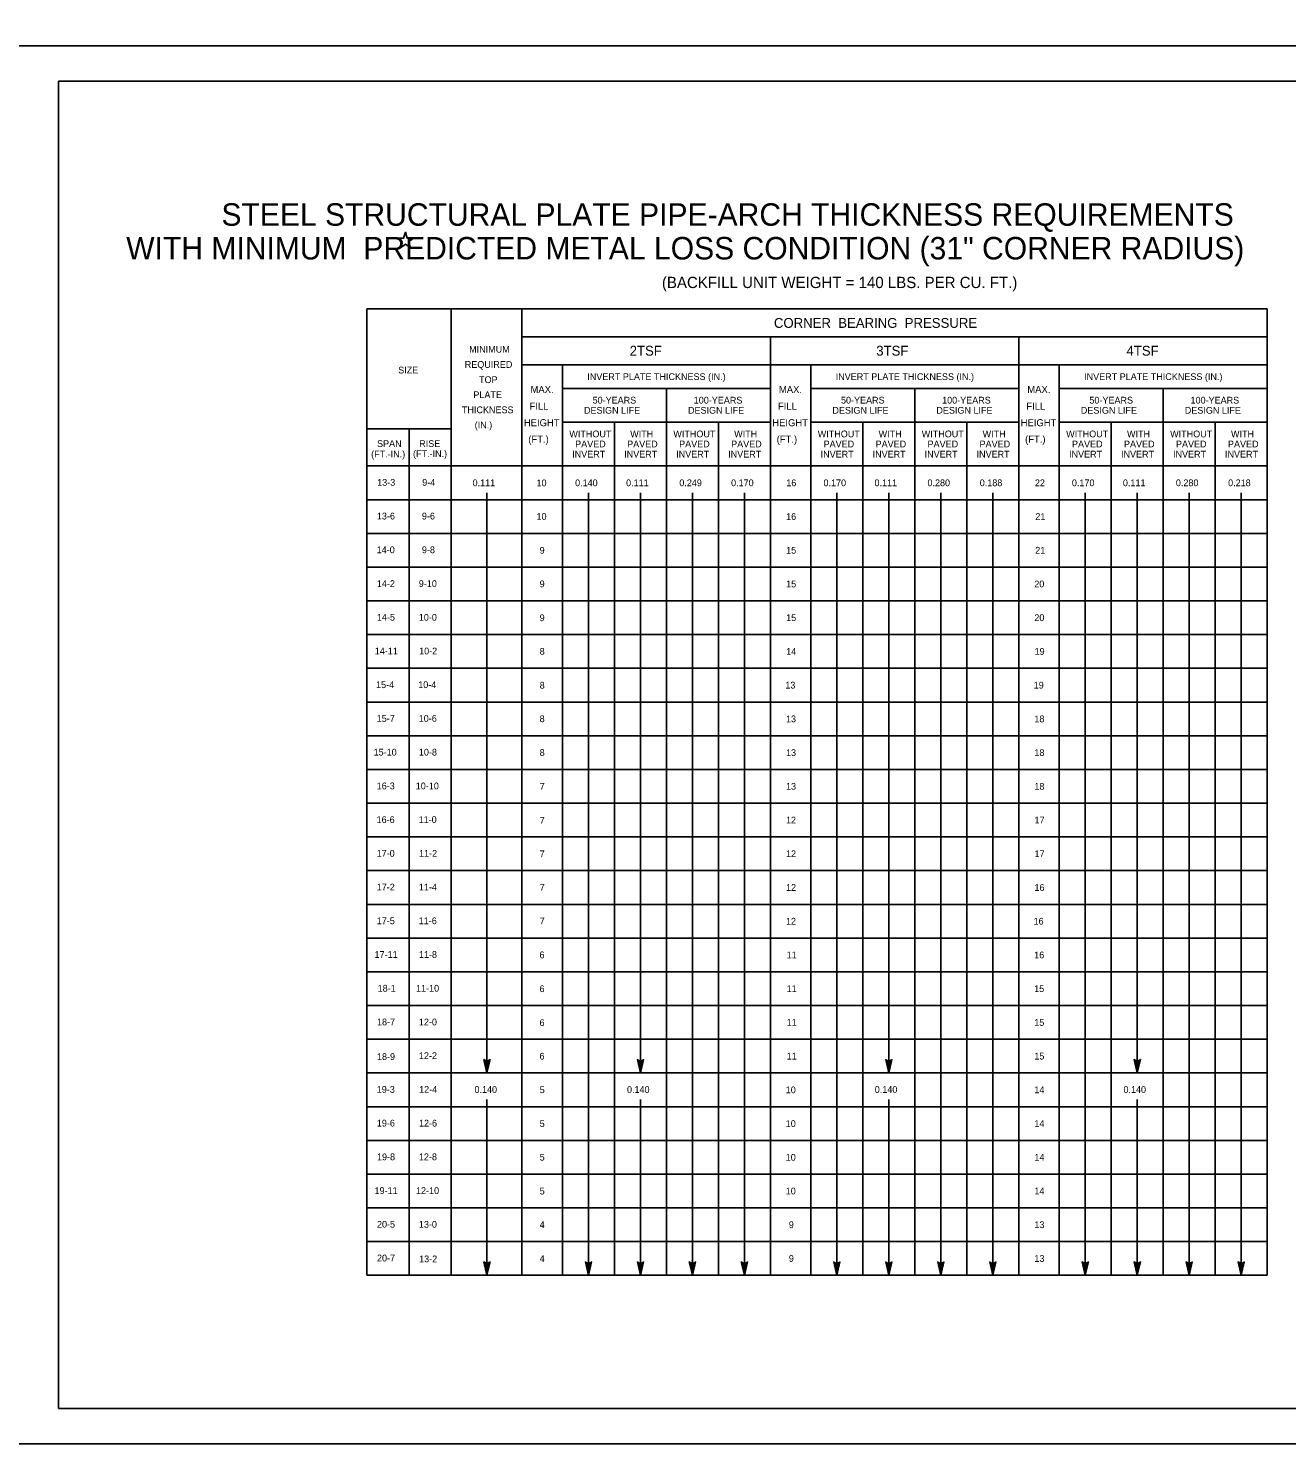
# Model space of a CAD drawing. Extents: x 591 to 2288, y -189 to 2187.
# Drawn here: x 1459 to 1994, y 405 to 1007 of the extents above; entities that cross this region are included whole.
import ezdxf

# ---------------------------------------------------------------- set-up
doc = ezdxf.new("R2010")
doc.units = 0
for name, color, linetype in [('1', 7, 'Continuous'), ('2', 7, 'Continuous'), ('PLT-BNDY', 7, 'Continuous')]:
    doc.layers.add(name, color=color, linetype=linetype)

msp = doc.modelspace()

# ---------------------------------------------------------------- linework, layer by layer
at = {"layer": '1'}
for p, q in [((1603.34, 887.46), (1985.97, 887.46)), ((1603.34, 887.46), (1603.34, 476.76)), ((1639.17, 887.46), (1639.17, 476.76)), ((1669.26, 887.46), (1669.26, 476.76)), ((1985.97, 887.46), (1985.97, 476.76)), ((1669.26, 875.59), (1985.97, 875.59)), ((1774.83, 875.59), (1774.83, 476.76)), ((1880.4, 875.59), (1880.4, 476.76)), ((1669.26, 863.72), (1774.83, 863.72)), ((1686.45, 863.72), (1686.45, 476.76)), ((1774.83, 863.72), (1880.4, 863.72)), ((1792.02, 863.72), (1792.02, 476.76)), ((1880.4, 863.72), (1985.97, 863.72)), ((1897.59, 863.72), (1897.59, 476.76)), ((1686.45, 853.69), (1774.83, 853.69)), ((1730.64, 853.69), (1730.64, 476.76)), ((1792.02, 853.69), (1880.4, 853.69)), ((1836.21, 853.69), (1836.21, 476.76)), ((1897.59, 853.69), (1985.97, 853.69)), ((1941.78, 853.69), (1941.78, 476.76)), ((1639.17, 836.49), (1603.34, 836.49)), ((1621.25, 836.49), (1621.25, 476.76)), ((1686.45, 839.36), (1730.64, 839.36)), ((1708.54, 839.36), (1708.54, 476.76)), ((1774.83, 839.36), (1730.64, 839.36)), ((1752.74, 839.36), (1752.74, 476.76)), ((1792.02, 839.36), (1836.21, 839.36)), ((1814.11, 839.36), (1814.11, 476.76)), ((1880.4, 839.36), (1836.21, 839.36)), ((1858.31, 839.36), (1858.31, 476.76)), ((1897.59, 839.36), (1941.78, 839.36)), ((1919.68, 839.36), (1919.68, 476.76)), ((1985.97, 839.36), (1941.78, 839.36)), ((1963.88, 839.36), (1963.88, 476.76)), ((1985.97, 820.72), (1603.34, 820.72)), ((1603.34, 806.39), (1985.97, 806.39)), ((1654.35, 809.3), (1654.35, 562.75)), ((1697.49, 809.3), (1697.49, 479.62)), ((1719.59, 809.3), (1719.59, 562.75)), ((1741.68, 809.3), (1741.68, 479.62)), ((1763.79, 809.3), (1763.79, 479.62)), ((1803.06, 809.3), (1803.06, 479.62)), ((1825.16, 809.3), (1825.16, 562.75)), ((1847.26, 809.3), (1847.26, 479.62)), ((1869.36, 809.3), (1869.36, 479.62)), ((1908.63, 809.3), (1908.63, 479.62)), ((1930.73, 809.3), (1930.73, 562.75)), ((1952.83, 809.3), (1952.83, 479.62)), ((1974.93, 809.3), (1974.93, 479.62)), ((1603.34, 792.06), (1985.97, 792.06)), ((1603.34, 777.73), (1985.97, 777.73)), ((1603.34, 763.4), (1985.97, 763.4)), ((1603.34, 749.06), (1985.97, 749.06)), ((1603.34, 734.73), (1985.97, 734.73)), ((1603.34, 720.4), (1985.97, 720.4)), ((1603.34, 706.07), (1985.97, 706.07)), ((1603.34, 691.74), (1985.97, 691.74)), ((1603.34, 677.4), (1985.97, 677.4)), ((1603.34, 663.07), (1985.97, 663.07)), ((1603.34, 648.74), (1985.97, 648.74)), ((1603.34, 634.41), (1985.97, 634.41)), ((1603.34, 620.08), (1985.97, 620.08)), ((1603.34, 605.74), (1985.97, 605.74)), ((1603.34, 591.41), (1985.97, 591.41)), ((1603.34, 577.08), (1985.97, 577.08)), ((1603.34, 562.75), (1985.97, 562.75)), ((1603.34, 548.42), (1985.97, 548.42)), ((1654.35, 479.62), (1654.35, 551.52)), ((1719.59, 479.62), (1719.59, 551.52)), ((1825.16, 479.62), (1825.16, 551.52)), ((1930.73, 479.62), (1930.73, 551.52)), ((1603.34, 534.08), (1985.97, 534.08)), ((1603.34, 519.75), (1985.97, 519.75)), ((1603.34, 505.42), (1985.97, 505.42)), ((1603.34, 491.09), (1985.97, 491.09)), ((1603.34, 476.76), (1985.97, 476.76))]:
    msp.add_line(p, q, dxfattribs=at)
for points in [[(1655.33, 568.17), (1654.77, 567.97), (1654.35, 562.75), (1655.33, 568.17), (1655.67, 568.45), (1654.35, 562.75), (1653.98, 567.97), (1653.42, 568.16), (1654.35, 562.75), (1653.05, 568.45), (1653.42, 568.16)], [(1720.57, 568.17), (1720.01, 567.97), (1719.59, 562.75), (1720.57, 568.17), (1720.92, 568.45), (1719.59, 562.75), (1719.22, 567.97), (1718.66, 568.16), (1719.59, 562.75), (1718.29, 568.45), (1718.66, 568.16)], [(1826.14, 568.17), (1825.58, 567.97), (1825.16, 562.75), (1826.14, 568.17), (1826.49, 568.45), (1825.16, 562.75), (1824.79, 567.97), (1824.23, 568.16), (1825.16, 562.75), (1823.86, 568.45), (1824.23, 568.16)], [(1931.71, 568.17), (1931.15, 567.97), (1930.73, 562.75), (1931.71, 568.17), (1932.06, 568.45), (1930.73, 562.75), (1930.36, 567.97), (1929.8, 568.16), (1930.73, 562.75), (1929.43, 568.45), (1929.8, 568.16)], [(1655.33, 482.18), (1654.77, 481.98), (1654.35, 476.76), (1655.33, 482.18), (1655.67, 482.46), (1654.35, 476.76), (1653.98, 481.98), (1653.42, 482.17), (1654.35, 476.76), (1653.05, 482.46), (1653.42, 482.17)], [(1698.47, 482.18), (1697.91, 481.98), (1697.49, 476.76), (1698.47, 482.18), (1698.81, 482.46), (1697.49, 476.76), (1697.12, 481.98), (1696.56, 482.17), (1697.49, 476.76), (1696.19, 482.46), (1696.56, 482.17)], [(1720.57, 482.18), (1720.01, 481.98), (1719.59, 476.76), (1720.57, 482.18), (1720.92, 482.46), (1719.59, 476.76), (1719.22, 481.98), (1718.66, 482.17), (1719.59, 476.76), (1718.29, 482.46), (1718.66, 482.17)], [(1742.66, 482.18), (1742.1, 481.98), (1741.68, 476.76), (1742.66, 482.18), (1743.01, 482.46), (1741.68, 476.76), (1741.31, 481.98), (1740.75, 482.17), (1741.68, 476.76), (1740.38, 482.46), (1740.75, 482.17)], [(1764.77, 482.18), (1764.2, 481.98), (1763.79, 476.76), (1764.77, 482.18), (1765.11, 482.46), (1763.79, 476.76), (1763.41, 481.98), (1762.85, 482.17), (1763.79, 476.76), (1762.48, 482.46), (1762.85, 482.17)], [(1804.04, 482.18), (1803.48, 481.98), (1803.06, 476.76), (1804.04, 482.18), (1804.39, 482.46), (1803.06, 476.76), (1802.69, 481.98), (1802.13, 482.17), (1803.06, 476.76), (1801.76, 482.46), (1802.13, 482.17)], [(1826.14, 482.18), (1825.58, 481.98), (1825.16, 476.76), (1826.14, 482.18), (1826.49, 482.46), (1825.16, 476.76), (1824.79, 481.98), (1824.23, 482.17), (1825.16, 476.76), (1823.86, 482.46), (1824.23, 482.17)], [(1848.24, 482.18), (1847.67, 481.98), (1847.26, 476.76), (1848.24, 482.18), (1848.58, 482.46), (1847.26, 476.76), (1846.88, 481.98), (1846.33, 482.17), (1847.26, 476.76), (1845.95, 482.46), (1846.33, 482.17)], [(1870.34, 482.18), (1869.77, 481.98), (1869.36, 476.76), (1870.34, 482.18), (1870.68, 482.46), (1869.36, 476.76), (1868.98, 481.98), (1868.42, 482.17), (1869.36, 476.76), (1868.05, 482.46), (1868.42, 482.17)], [(1909.61, 482.18), (1909.05, 481.98), (1908.63, 476.76), (1909.61, 482.18), (1909.96, 482.46), (1908.63, 476.76), (1908.26, 481.98), (1907.7, 482.17), (1908.63, 476.76), (1907.33, 482.46), (1907.7, 482.17)], [(1931.71, 482.18), (1931.15, 481.98), (1930.73, 476.76), (1931.71, 482.18), (1932.06, 482.46), (1930.73, 476.76), (1930.36, 481.98), (1929.8, 482.17), (1930.73, 476.76), (1929.43, 482.46), (1929.8, 482.17)], [(1953.81, 482.18), (1953.24, 481.98), (1952.83, 476.76), (1953.81, 482.18), (1954.15, 482.46), (1952.83, 476.76), (1952.45, 481.98), (1951.9, 482.17), (1952.83, 476.76), (1951.52, 482.46), (1951.9, 482.17)], [(1975.91, 482.18), (1975.34, 481.98), (1974.93, 476.76), (1975.91, 482.18), (1976.25, 482.46), (1974.93, 476.76), (1974.56, 481.98), (1973.99, 482.17), (1974.93, 476.76), (1973.62, 482.46), (1973.99, 482.17)]]:
    msp.add_lwpolyline(points, dxfattribs=at)
at = {"layer": '2'}
for p, q in [((1472.34, 420.21), (1472.34, 984.21)), ((1472.34, 984.21), (2258.34, 984.21)), ((1619.7, 916.41), (1619.7, 916.41)), ((2258.34, 420.21), (1472.34, 420.21))]:
    msp.add_line(p, q, dxfattribs=at)
msp.add_lwpolyline([(1616.27, 917.52), (1618.91, 917.51), (1619.73, 920.03), (1620.53, 917.49), (1623.18, 917.52), (1621.02, 915.96), (1621.86, 913.47), (1619.7, 915.02), (1617.59, 913.47), (1618.41, 915.97), (1616.27, 917.52)], dxfattribs=at)
at = {"layer": 'PLT-BNDY'}
for points in [[(1432.34, 1593.21), (2273.34, 1593.21), (2273.34, 999.21), (1432.34, 999.21)], [(1432.34, 405.21), (2273.34, 405.21), (2273.34, 999.21), (1432.34, 999.21)]]:
    msp.add_lwpolyline(points, close=True, dxfattribs=at)

# ---------------------------------------------------------------- texts
at = {"layer": '1'}
for s, height, p in [('STEEL STRUCTURAL PLATE PIPE-ARCH THICKNESS REQUIREMENTS', 9.5546, (1541.53, 922.8)), ('WITH MINIMUM  PREDICTED METAL LOSS CONDITION (31" CORNER RADIUS)', 9.5546, (1501.06, 908.48)), ('(BACKFILL UNIT WEIGHT = 140 LBS. PER CU. FT.)', 4.7773, (1728.73, 896.32)), ('CORNER  BEARING  PRESSURE', 4.1801, (1776.34, 879.41)), ('MINIMUM', 2.866, (1646.8, 868.9)), ('2TSF', 4.18, (1715.03, 867.6)), ('3TSF', 4.18, (1819.82, 867.6)), ('4TSF', 4.18, (1926.17, 867.6)), ('SIZE', 2.866, (1616.66, 860.03)), ('REQUIRED', 2.866, (1644.94, 862.42)), ('INVERT PLATE THICKNESS (IN.)', 2.8664, (1697.02, 857.24)), ('INVERT PLATE THICKNESS (IN.)', 2.8664, (1802.59, 857.24)), ('INVERT PLATE THICKNESS (IN.)', 2.8664, (1908.16, 857.24)), ('TOP', 2.866, (1651.02, 855.94)), ('PLATE', 2.866, (1648.6, 849.54)), ('50-YEARS', 2.866, (1699.27, 847.24)), ('100-YEARS', 2.866, (1742.25, 847.24)), ('50-YEARS', 2.866, (1804.84, 847.24)), ('100-YEARS', 2.866, (1847.82, 847.24)), ('50-YEARS', 2.866, (1910.41, 847.24)), ('100-YEARS', 2.866, (1953.39, 847.24)), ('THICKNESS', 2.866, (1643.73, 843.14)), ('DESIGN LIFE', 2.8664, (1695.62, 842.94)), ('DESIGN LIFE', 2.8664, (1739.81, 842.94)), ('DESIGN LIFE', 2.8664, (1801.19, 842.94)), ('DESIGN LIFE', 2.8664, (1845.38, 842.94)), ('DESIGN LIFE', 2.8664, (1906.76, 842.94)), ('DESIGN LIFE', 2.8664, (1950.95, 842.94)), ('(IN.)', 2.866, (1649.16, 836.73)), ('SPAN', 2.866, (1607.67, 828.79)), ('RISE', 2.866, (1625.59, 828.79)), ('WITHOUT', 2.866, (1689.38, 832.9)), ('PAVED', 2.866, (1691.87, 828.61)), ('PAVED', 2.866, (1713.97, 828.61)), ('WITH', 2.866, (1715.25, 832.9)), ('WITHOUT', 2.866, (1733.58, 832.9)), ('PAVED', 2.866, (1736.06, 828.61)), ('PAVED', 2.866, (1758.16, 828.61)), ('WITH', 2.866, (1759.44, 832.9)), ('WITHOUT', 2.866, (1794.96, 832.9)), ('PAVED', 2.866, (1797.44, 828.61)), ('PAVED', 2.866, (1819.54, 828.61)), ('WITH', 2.866, (1820.82, 832.9)), ('WITHOUT', 2.866, (1839.15, 832.9)), ('PAVED', 2.866, (1841.63, 828.61)), ('PAVED', 2.866, (1863.73, 828.61)), ('WITH', 2.866, (1865.02, 832.9)), ('WITHOUT', 2.866, (1900.53, 832.9)), ('PAVED', 2.866, (1903.01, 828.61)), ('PAVED', 2.866, (1925.11, 828.61)), ('WITH', 2.866, (1926.39, 832.9)), ('WITHOUT', 2.866, (1944.72, 832.9)), ('PAVED', 2.866, (1947.2, 828.61)), ('PAVED', 2.866, (1969.3, 828.61)), ('WITH', 2.866, (1970.59, 832.9)), ('(FT.-IN.)', 2.866, (1605.15, 824.32)), ('(FT.-IN.)', 2.866, (1622.96, 824.53)), ('INVERT', 2.866, (1690.6, 824.31)), ('INVERT', 2.866, (1712.7, 824.31)), ('INVERT', 2.866, (1734.8, 824.31)), ('INVERT', 2.866, (1756.89, 824.31)), ('INVERT', 2.866, (1796.18, 824.31)), ('INVERT', 2.866, (1818.27, 824.31)), ('INVERT', 2.866, (1840.37, 824.31)), ('INVERT', 2.866, (1862.46, 824.31)), ('INVERT', 2.866, (1901.75, 824.31)), ('INVERT', 2.866, (1923.84, 824.31)), ('INVERT', 2.866, (1945.94, 824.31)), ('INVERT', 2.866, (1968.03, 824.31)), ('13-3', 2.866, (1607.73, 812.31)), ('9-4', 2.866, (1626.87, 812.31)), ('0.111', 2.866, (1648.27, 812.12)), ('10', 2.866, (1675.45, 812.09)), ('0.140', 2.866, (1691.83, 812.12)), ('0.111', 2.866, (1713.5, 812.12)), ('0.249', 2.866, (1736.12, 812.12)), ('0.170', 2.866, (1758.12, 812.12)), ('16', 2.866, (1781.59, 812.12)), ('0.170', 2.866, (1797.4, 812.12)), ('0.111', 2.866, (1819.08, 812.12)), ('0.280', 2.866, (1841.59, 812.12)), ('0.188', 2.866, (1863.8, 812.12)), ('22', 2.866, (1887.23, 812.12)), ('0.170', 2.866, (1902.97, 812.12)), ('0.111', 2.866, (1924.65, 812.12)), ('0.280', 2.866, (1947.16, 812.12)), ('0.218', 2.866, (1969.37, 812.12)), ('13-6', 2.866, (1607.6, 797.98)), ('9-6', 2.866, (1626.73, 797.98)), ('10', 2.866, (1675.45, 797.83)), ('16', 2.866, (1781.52, 797.79)), ('21', 2.866, (1887.44, 797.79)), ('14-0', 2.866, (1607.5, 783.65)), ('9-8', 2.866, (1626.73, 783.65)), ('9', 2.87, (1676.77, 783.43)), ('15', 2.866, (1781.52, 783.46)), ('21', 2.866, (1887.38, 783.46)), ('14-2', 2.866, (1607.6, 769.31)), ('9-10', 2.866, (1625.41, 769.31)), ('9', 2.87, (1676.77, 769.17)), ('15', 2.866, (1781.52, 769.13)), ('20', 2.866, (1886.99, 769.13)), ('10-0', 2.866, (1625.42, 754.98)), ('14-5', 2.866, (1607.61, 754.98)), ('9', 2.87, (1676.77, 754.76)), ('15', 2.866, (1781.53, 754.8)), ('20', 2.866, (1887, 754.8)), ('14-11', 2.866, (1606.7, 740.65)), ('10-2', 2.866, (1625.55, 740.65)), ('8', 2.87, (1676.78, 740.5)), ('14', 2.866, (1781.56, 740.46)), ('19', 2.866, (1887.12, 740.46)), ('15-4', 2.866, (1607.25, 726.32)), ('10-4', 2.866, (1625.17, 726.32)), ('8', 2.87, (1676.78, 726.1)), ('13', 2.866, (1781.18, 726.13)), ('19', 2.866, (1886.74, 726.13)), ('15-7', 2.866, (1607.53, 711.99)), ('10-6', 2.866, (1625.38, 711.99)), ('8', 2.87, (1676.78, 711.84)), ('13', 2.866, (1781.46, 711.8)), ('18', 2.866, (1887.03, 711.8)), ('15-10', 2.866, (1606.21, 697.65)), ('10-8', 2.866, (1625.45, 697.65)), ('8', 2.87, (1676.78, 697.51)), ('13', 2.866, (1781.46, 697.47)), ('18', 2.866, (1887.03, 697.47)), ('16-3', 2.866, (1607.53, 683.32)), ('10-10', 2.866, (1624.13, 683.32)), ('7', 2.87, (1676.78, 683.1)), ('13', 2.866, (1781.46, 683.14)), ('18', 2.866, (1887.03, 683.14)), ('16-6', 2.866, (1607.47, 668.99)), ('11-0', 2.866, (1625.34, 668.99)), ('7', 2.87, (1676.78, 668.69)), ('12', 2.866, (1781.46, 668.81)), ('17', 2.866, (1887.09, 668.81)), ('17-0', 2.866, (1607.5, 654.66)), ('11-2', 2.866, (1625.52, 654.66)), ('7', 2.87, (1676.78, 654.44)), ('12', 2.866, (1781.46, 654.47)), ('17', 2.866, (1887.1, 654.47)), ('17-2', 2.866, (1607.53, 640.33)), ('11-4', 2.866, (1625.45, 640.33)), ('7', 2.87, (1676.78, 640.18)), ('12', 2.866, (1781.46, 640.14)), ('16', 2.866, (1887.06, 640.14)), ('17-5', 2.866, (1607.53, 625.99)), ('11-6', 2.866, (1625.38, 625.99)), ('7', 2.87, (1676.78, 625.92)), ('12', 2.866, (1781.46, 625.81)), ('16', 2.866, (1886.68, 625.81)), ('17-11', 2.866, (1606.61, 611.66)), ('11-8', 2.866, (1625.46, 611.66)), ('6', 2.87, (1676.71, 611.52)), ('11', 2.866, (1781.74, 611.48)), ('16', 2.866, (1886.96, 611.48)), ('18-1', 2.866, (1607.92, 597.33)), ('11-10', 2.866, (1624.23, 597.33)), ('6', 2.87, (1676.71, 597.11)), ('11', 2.866, (1781.74, 597.15)), ('15', 2.866, (1886.94, 597.15)), ('18-7', 2.866, (1607.64, 583)), ('12-0', 2.866, (1625.45, 583)), ('6', 2.87, (1676.71, 582.7)), ('11', 2.866, (1781.74, 582.81)), ('15', 2.866, (1886.97, 582.81)), ('12-2', 2.866, (1625.46, 568.67)), ('18-9', 2.866, (1607.63, 568.3)), ('6', 2.87, (1676.71, 568.45)), ('11', 2.866, (1781.74, 568.48)), ('15', 2.866, (1887, 568.48)), ('19-3', 2.866, (1607.54, 554.33)), ('12-4', 2.866, (1625.55, 554.33)), ('0.140', 2.866, (1649.07, 554.29)), ('5', 2.87, (1676.78, 554.19)), ('0.140', 2.866, (1713.89, 554.29)), ('10', 2.866, (1781.35, 554.15)), ('0.140', 2.866, (1819.2, 554.29)), ('14', 2.866, (1887.03, 554.15)), ('0.140', 2.866, (1924.88, 554.29)), ('19-6', 2.866, (1607.57, 540)), ('12-6', 2.866, (1625.49, 540)), ('5', 2.87, (1676.78, 539.78)), ('10', 2.866, (1781.35, 539.82)), ('14', 2.866, (1887.03, 539.82)), ('19-8', 2.866, (1607.64, 525.67)), ('12-8', 2.866, (1625.46, 525.67)), ('5', 2.87, (1676.78, 525.52)), ('10', 2.866, (1781.35, 525.49)), ('14', 2.866, (1887.03, 525.49)), ('19-11', 2.866, (1606.61, 511.34)), ('12-10', 2.866, (1624.23, 511.34)), ('5', 2.87, (1676.78, 511.12)), ('10', 2.866, (1781.35, 511.15)), ('14', 2.866, (1887.03, 511.15)), ('20-5', 2.866, (1607.64, 497.01)), ('13-0', 2.866, (1625.45, 497.01)), ('4', 2.87, (1676.78, 496.86)), ('9', 2.87, (1782.66, 496.82)), ('13', 2.866, (1887.03, 496.82)), ('20-7', 2.866, (1607.64, 482.67)), ('13-2', 2.866, (1625.55, 482.3)), ('4', 2.87, (1676.78, 482.45)), ('9', 2.87, (1782.66, 482.49)), ('13', 2.866, (1887.03, 482.49))]:
    msp.add_text(s, height=height, dxfattribs=at).set_placement(p)
at = {"layer": '2'}
for s, p in [('MAX.', (1672.89, 851.73)), ('MAX.', (1778.46, 851.73)), ('MAX.', (1884.03, 851.73)), ('FILL', (1672.47, 844.6)), ('FILL', (1778.04, 844.6)), ('FILL', (1883.61, 844.6)), ('HEIGHT', (1670.07, 837.6)), ('HEIGHT', (1775.64, 837.6)), ('HEIGHT', (1881.21, 837.6)), ('(FT.)', (1671.94, 830.6)), ('(FT.)', (1777.51, 830.6)), ('(FT.)', (1883.08, 830.6))]:
    msp.add_text(s, height=3, dxfattribs=at).set_placement(p)

doc.saveas('drawing.dxf')
